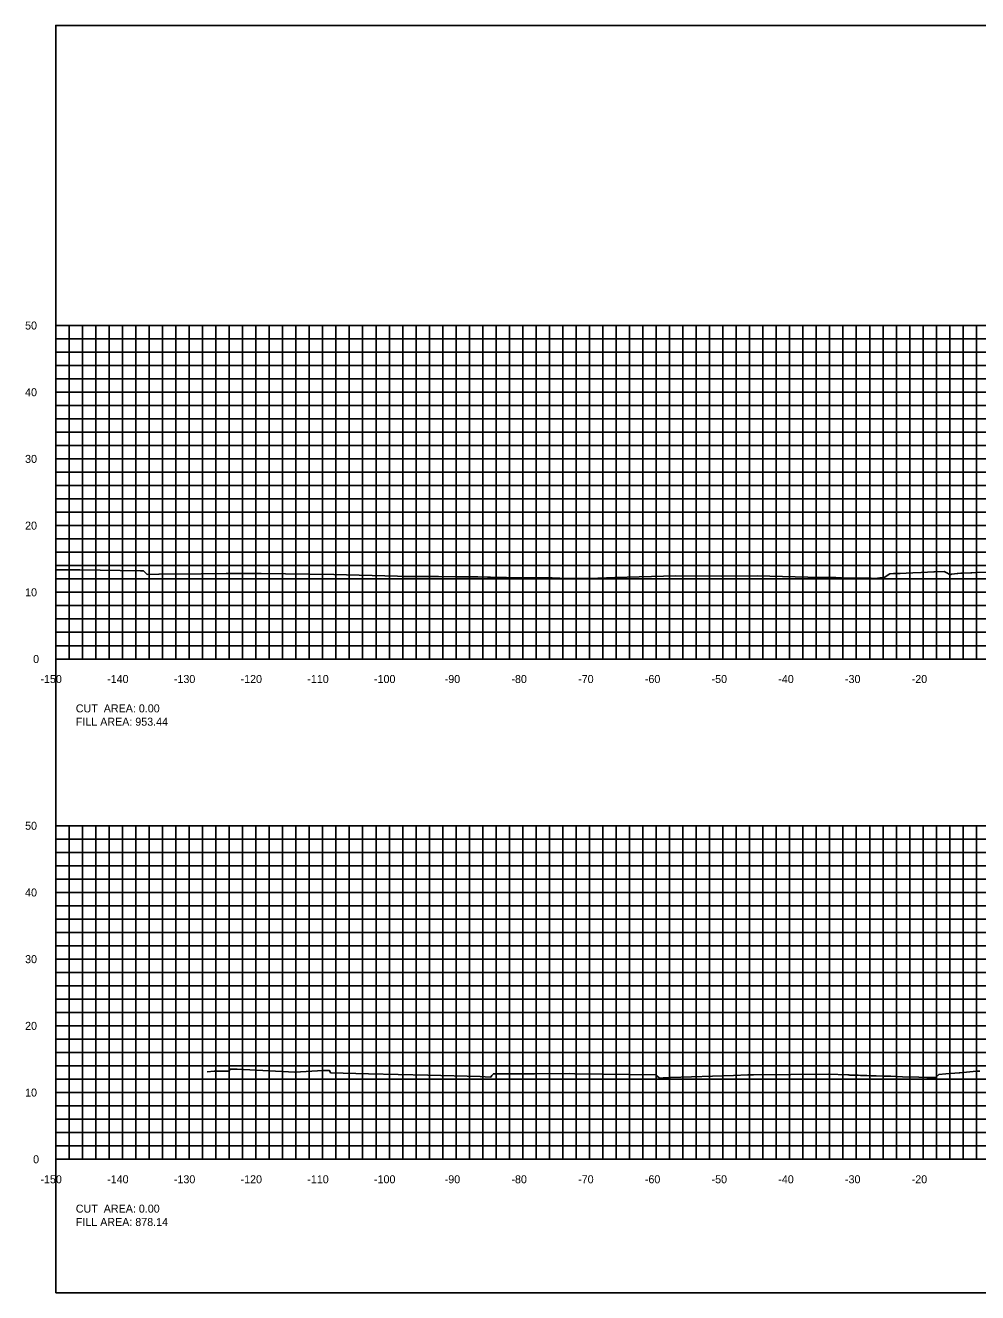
# Model space of a CAD drawing. Extents: x 1797714 to 1804825, y 249015 to 250269.
# Drawn here: x 1804176.4 to 1804319.2, y 250079.4 to 250269.4 of the extents above; entities that cross this region are included whole.
import ezdxf

# ---------------------------------------------------------------- set-up
doc = ezdxf.new("R2010")
doc.units = 0
for name, color, linetype in [('10', 7, 'Continuous'), ('31', 7, 'Continuous'), ('60', 7, 'Continuous'), ('ANNO-TXT', 7, 'Continuous'), ('Level 62', 7, 'Continuous'), ('M-ROADS', 7, 'Continuous')]:
    doc.layers.add(name, color=color, linetype=linetype)

msp = doc.modelspace()

# ---------------------------------------------------------------- linework, layer by layer
msp.add_lwpolyline([(1804181, 250079.43), (1804481, 250079.43), (1804481, 250269.43), (1804181, 250269.43)], close=True)
at = {"layer": '60'}
for p, q in [((1804180.94, 250224.43), (1804181, 250224.43)), ((1804181, 250174.43), (1804181, 250224.43)), ((1804180.94, 250214.43), (1804181, 250214.43)), ((1804180.94, 250204.43), (1804181, 250204.43)), ((1804180.94, 250194.43), (1804181, 250194.43)), ((1804180.94, 250184.43), (1804181, 250184.43)), ((1804180.94, 250174.43), (1804181, 250174.43)), ((1804181, 250174.43), (1804481, 250174.43)), ((1804181, 250174.37), (1804181, 250174.43)), ((1804191, 250174.37), (1804191, 250174.43)), ((1804201, 250174.37), (1804201, 250174.43)), ((1804211, 250174.37), (1804211, 250174.43)), ((1804221, 250174.37), (1804221, 250174.43)), ((1804231, 250174.37), (1804231, 250174.43)), ((1804241, 250174.37), (1804241, 250174.43)), ((1804251, 250174.37), (1804251, 250174.43)), ((1804261, 250174.37), (1804261, 250174.43)), ((1804271, 250174.37), (1804271, 250174.43)), ((1804281, 250174.37), (1804281, 250174.43)), ((1804291, 250174.37), (1804291, 250174.43)), ((1804301, 250174.37), (1804301, 250174.43)), ((1804311, 250174.37), (1804311, 250174.43)), ((1804180.94, 250149.43), (1804181, 250149.43)), ((1804181, 250099.43), (1804181, 250149.43)), ((1804180.94, 250139.43), (1804181, 250139.43)), ((1804180.94, 250129.43), (1804181, 250129.43)), ((1804180.94, 250119.43), (1804181, 250119.43)), ((1804180.94, 250109.43), (1804181, 250109.43)), ((1804180.94, 250099.43), (1804181, 250099.43)), ((1804181, 250099.43), (1804481, 250099.43)), ((1804181, 250099.37), (1804181, 250099.43)), ((1804191, 250099.37), (1804191, 250099.43)), ((1804201, 250099.37), (1804201, 250099.43)), ((1804211, 250099.37), (1804211, 250099.43)), ((1804221, 250099.37), (1804221, 250099.43)), ((1804231, 250099.37), (1804231, 250099.43)), ((1804241, 250099.37), (1804241, 250099.43)), ((1804251, 250099.37), (1804251, 250099.43)), ((1804261, 250099.37), (1804261, 250099.43)), ((1804271, 250099.37), (1804271, 250099.43)), ((1804281, 250099.37), (1804281, 250099.43)), ((1804291, 250099.37), (1804291, 250099.43)), ((1804301, 250099.37), (1804301, 250099.43)), ((1804311, 250099.37), (1804311, 250099.43))]:
    msp.add_line(p, q, dxfattribs=at)
at = {"layer": 'Level 62'}
for p, q in [((1804181, 250224.43), (1804481, 250224.43)), ((1804181, 250174.43), (1804181, 250224.43)), ((1804183, 250174.43), (1804183, 250224.43)), ((1804185, 250174.43), (1804185, 250224.43)), ((1804187, 250174.43), (1804187, 250224.43)), ((1804189, 250174.43), (1804189, 250224.43)), ((1804191, 250174.43), (1804191, 250224.43)), ((1804193, 250174.43), (1804193, 250224.43)), ((1804195, 250174.43), (1804195, 250224.43)), ((1804197, 250174.43), (1804197, 250224.43)), ((1804199, 250174.43), (1804199, 250224.43)), ((1804201, 250174.43), (1804201, 250224.43)), ((1804203, 250174.43), (1804203, 250224.43)), ((1804205, 250174.43), (1804205, 250224.43)), ((1804207, 250174.43), (1804207, 250224.43)), ((1804209, 250174.43), (1804209, 250224.43)), ((1804211, 250174.43), (1804211, 250224.43)), ((1804213, 250174.43), (1804213, 250224.43)), ((1804215, 250174.43), (1804215, 250224.43)), ((1804217, 250174.43), (1804217, 250224.43)), ((1804219, 250174.43), (1804219, 250224.43)), ((1804221, 250174.43), (1804221, 250224.43)), ((1804223, 250174.43), (1804223, 250224.43)), ((1804225, 250174.43), (1804225, 250224.43)), ((1804227, 250174.43), (1804227, 250224.43)), ((1804229, 250174.43), (1804229, 250224.43)), ((1804231, 250174.43), (1804231, 250224.43)), ((1804233, 250174.43), (1804233, 250224.43)), ((1804235, 250174.43), (1804235, 250224.43)), ((1804237, 250174.43), (1804237, 250224.43)), ((1804239, 250174.43), (1804239, 250224.43)), ((1804241, 250174.43), (1804241, 250224.43)), ((1804243, 250174.43), (1804243, 250224.43)), ((1804245, 250174.43), (1804245, 250224.43)), ((1804247, 250174.43), (1804247, 250224.43)), ((1804249, 250174.43), (1804249, 250224.43)), ((1804251, 250174.43), (1804251, 250224.43)), ((1804253, 250174.43), (1804253, 250224.43)), ((1804255, 250174.43), (1804255, 250224.43)), ((1804257, 250174.43), (1804257, 250224.43)), ((1804259, 250174.43), (1804259, 250224.43)), ((1804261, 250174.43), (1804261, 250224.43)), ((1804263, 250174.43), (1804263, 250224.43)), ((1804265, 250174.43), (1804265, 250224.43)), ((1804267, 250174.43), (1804267, 250224.43)), ((1804269, 250174.43), (1804269, 250224.43)), ((1804271, 250174.43), (1804271, 250224.43)), ((1804273, 250174.43), (1804273, 250224.43)), ((1804275, 250174.43), (1804275, 250224.43)), ((1804277, 250174.43), (1804277, 250224.43)), ((1804279, 250174.43), (1804279, 250224.43)), ((1804281, 250174.43), (1804281, 250224.43)), ((1804283, 250174.43), (1804283, 250224.43)), ((1804285, 250174.43), (1804285, 250224.43)), ((1804287, 250174.43), (1804287, 250224.43)), ((1804289, 250174.43), (1804289, 250224.43)), ((1804291, 250174.43), (1804291, 250224.43)), ((1804293, 250174.43), (1804293, 250224.43)), ((1804295, 250174.43), (1804295, 250224.43)), ((1804297, 250174.43), (1804297, 250224.43)), ((1804299, 250174.43), (1804299, 250224.43)), ((1804301, 250174.43), (1804301, 250224.43)), ((1804303, 250174.43), (1804303, 250224.43)), ((1804305, 250174.43), (1804305, 250224.43)), ((1804307, 250174.43), (1804307, 250224.43)), ((1804309, 250174.43), (1804309, 250224.43)), ((1804311, 250174.43), (1804311, 250224.43)), ((1804313, 250174.43), (1804313, 250224.43)), ((1804315, 250174.43), (1804315, 250224.43)), ((1804317, 250174.43), (1804317, 250224.43)), ((1804319, 250174.43), (1804319, 250224.43)), ((1804181, 250222.43), (1804481, 250222.43)), ((1804181, 250220.43), (1804481, 250220.43)), ((1804181, 250218.43), (1804481, 250218.43)), ((1804181, 250216.43), (1804481, 250216.43)), ((1804181, 250214.43), (1804481, 250214.43)), ((1804181, 250212.43), (1804481, 250212.43)), ((1804181, 250210.43), (1804481, 250210.43)), ((1804181, 250208.43), (1804481, 250208.43)), ((1804181, 250206.43), (1804481, 250206.43)), ((1804181, 250204.43), (1804481, 250204.43)), ((1804181, 250202.43), (1804481, 250202.43)), ((1804181, 250200.43), (1804481, 250200.43)), ((1804181, 250198.43), (1804481, 250198.43)), ((1804181, 250196.43), (1804481, 250196.43)), ((1804181, 250194.43), (1804481, 250194.43)), ((1804181, 250192.43), (1804481, 250192.43)), ((1804181, 250190.43), (1804481, 250190.43)), ((1804181, 250188.43), (1804481, 250188.43)), ((1804181, 250186.43), (1804481, 250186.43)), ((1804181, 250184.43), (1804481, 250184.43)), ((1804181, 250182.43), (1804481, 250182.43)), ((1804181, 250180.43), (1804481, 250180.43)), ((1804181, 250178.43), (1804481, 250178.43)), ((1804181, 250176.43), (1804481, 250176.43)), ((1804181, 250174.43), (1804481, 250174.43)), ((1804181, 250149.43), (1804481, 250149.43)), ((1804181, 250099.43), (1804181, 250149.43)), ((1804183, 250099.43), (1804183, 250149.43)), ((1804185, 250099.43), (1804185, 250149.43)), ((1804187, 250099.43), (1804187, 250149.43)), ((1804189, 250099.43), (1804189, 250149.43)), ((1804191, 250099.43), (1804191, 250149.43)), ((1804193, 250099.43), (1804193, 250149.43)), ((1804195, 250099.43), (1804195, 250149.43)), ((1804197, 250099.43), (1804197, 250149.43)), ((1804199, 250099.43), (1804199, 250149.43)), ((1804201, 250099.43), (1804201, 250149.43)), ((1804203, 250099.43), (1804203, 250149.43)), ((1804205, 250099.43), (1804205, 250149.43)), ((1804207, 250099.43), (1804207, 250149.43)), ((1804209, 250099.43), (1804209, 250149.43)), ((1804211, 250099.43), (1804211, 250149.43)), ((1804213, 250099.43), (1804213, 250149.43)), ((1804215, 250099.43), (1804215, 250149.43)), ((1804217, 250099.43), (1804217, 250149.43)), ((1804219, 250099.43), (1804219, 250149.43)), ((1804221, 250099.43), (1804221, 250149.43)), ((1804223, 250099.43), (1804223, 250149.43)), ((1804225, 250099.43), (1804225, 250149.43)), ((1804227, 250099.43), (1804227, 250149.43)), ((1804229, 250099.43), (1804229, 250149.43)), ((1804231, 250099.43), (1804231, 250149.43)), ((1804233, 250099.43), (1804233, 250149.43)), ((1804235, 250099.43), (1804235, 250149.43)), ((1804237, 250099.43), (1804237, 250149.43)), ((1804239, 250099.43), (1804239, 250149.43)), ((1804241, 250099.43), (1804241, 250149.43)), ((1804243, 250099.43), (1804243, 250149.43)), ((1804245, 250099.43), (1804245, 250149.43)), ((1804247, 250099.43), (1804247, 250149.43)), ((1804249, 250099.43), (1804249, 250149.43)), ((1804251, 250099.43), (1804251, 250149.43)), ((1804253, 250099.43), (1804253, 250149.43)), ((1804255, 250099.43), (1804255, 250149.43)), ((1804257, 250099.43), (1804257, 250149.43)), ((1804259, 250099.43), (1804259, 250149.43)), ((1804261, 250099.43), (1804261, 250149.43)), ((1804263, 250099.43), (1804263, 250149.43)), ((1804265, 250099.43), (1804265, 250149.43)), ((1804267, 250099.43), (1804267, 250149.43)), ((1804269, 250099.43), (1804269, 250149.43)), ((1804271, 250099.43), (1804271, 250149.43)), ((1804273, 250099.43), (1804273, 250149.43)), ((1804275, 250099.43), (1804275, 250149.43)), ((1804277, 250099.43), (1804277, 250149.43)), ((1804279, 250099.43), (1804279, 250149.43)), ((1804281, 250099.43), (1804281, 250149.43)), ((1804283, 250099.43), (1804283, 250149.43)), ((1804285, 250099.43), (1804285, 250149.43)), ((1804287, 250099.43), (1804287, 250149.43)), ((1804289, 250099.43), (1804289, 250149.43)), ((1804291, 250099.43), (1804291, 250149.43)), ((1804293, 250099.43), (1804293, 250149.43)), ((1804295, 250099.43), (1804295, 250149.43)), ((1804297, 250099.43), (1804297, 250149.43)), ((1804299, 250099.43), (1804299, 250149.43)), ((1804301, 250099.43), (1804301, 250149.43)), ((1804303, 250099.43), (1804303, 250149.43)), ((1804305, 250099.43), (1804305, 250149.43)), ((1804307, 250099.43), (1804307, 250149.43)), ((1804309, 250099.43), (1804309, 250149.43)), ((1804311, 250099.43), (1804311, 250149.43)), ((1804313, 250099.43), (1804313, 250149.43)), ((1804315, 250099.43), (1804315, 250149.43)), ((1804317, 250099.43), (1804317, 250149.43)), ((1804319, 250099.43), (1804319, 250149.43)), ((1804181, 250147.43), (1804481, 250147.43)), ((1804181, 250145.43), (1804481, 250145.43)), ((1804181, 250143.43), (1804481, 250143.43)), ((1804181, 250141.43), (1804481, 250141.43)), ((1804181, 250139.43), (1804481, 250139.43)), ((1804181, 250137.43), (1804481, 250137.43)), ((1804181, 250135.43), (1804481, 250135.43)), ((1804181, 250133.43), (1804481, 250133.43)), ((1804181, 250131.43), (1804481, 250131.43)), ((1804181, 250129.43), (1804481, 250129.43)), ((1804181, 250127.43), (1804481, 250127.43)), ((1804181, 250125.43), (1804481, 250125.43)), ((1804181, 250123.43), (1804481, 250123.43)), ((1804181, 250121.43), (1804481, 250121.43)), ((1804181, 250119.43), (1804481, 250119.43)), ((1804181, 250117.43), (1804481, 250117.43)), ((1804181, 250115.43), (1804481, 250115.43)), ((1804181, 250113.43), (1804481, 250113.43)), ((1804181, 250111.43), (1804481, 250111.43)), ((1804181, 250109.43), (1804481, 250109.43)), ((1804181, 250107.43), (1804481, 250107.43)), ((1804181, 250105.43), (1804481, 250105.43)), ((1804181, 250103.43), (1804481, 250103.43)), ((1804181, 250101.43), (1804481, 250101.43)), ((1804181, 250099.43), (1804481, 250099.43))]:
    msp.add_line(p, q, dxfattribs=at)
at = {"layer": 'M-ROADS'}
for points in [[(1804181, 250187.82), (1804184.59, 250187.78), (1804193.71, 250187.67), (1804194.13, 250187.66), (1804194.66, 250187.13), (1804194.68, 250187.11), (1804196.43, 250187.16), (1804196.5, 250187.16), (1804202.8, 250187.21), (1804206.53, 250187.24), (1804207.9, 250187.24), (1804208.44, 250187.25), (1804209.12, 250187.25), (1804211.79, 250187.25), (1804222.67, 250187.08), (1804232.2, 250186.83), (1804233.13, 250186.82), (1804234.22, 250186.81), (1804236.94, 250186.79), (1804238.38, 250186.78), (1804241.05, 250186.74), (1804242.72, 250186.74), (1804243.89, 250186.74), (1804244.09, 250186.74), (1804244.26, 250186.73), (1804245.73, 250186.69), (1804246.18, 250186.68), (1804247.1, 250186.66), (1804247.45, 250186.65), (1804248.18, 250186.64), (1804248.31, 250186.64), (1804248.55, 250186.64), (1804250.03, 250186.62), (1804250.14, 250186.62), (1804250.89, 250186.61), (1804251.24, 250186.61), (1804252.56, 250186.6), (1804253.55, 250186.6), (1804254.06, 250186.6), (1804255.2, 250186.6), (1804255.42, 250186.59), (1804257.7, 250186.52), (1804257.74, 250186.52), (1804257.77, 250186.52), (1804259.37, 250186.49), (1804259.48, 250186.5), (1804261.02, 250186.52), (1804264.82, 250186.63), (1804273.92, 250186.89), (1804280.86, 250186.86), (1804286.13, 250186.89), (1804295.64, 250186.67), (1804296.13, 250186.66), (1804296.66, 250186.65), (1804297.25, 250186.64), (1804297.92, 250186.63), (1804298.66, 250186.62), (1804298.79, 250186.62), (1804301.18, 250186.54), (1804301.64, 250186.54), (1804301.64, 250186.54), (1804301.85, 250186.55), (1804302.27, 250186.57), (1804302.92, 250186.57), (1804303.06, 250186.55), (1804303.2, 250186.54), (1804303.52, 250186.51), (1804303.62, 250186.51), (1804303.72, 250186.52), (1804304.15, 250186.57), (1804305.29, 250186.68), (1804305.49, 250186.86), (1804306.02, 250187.2), (1804306.57, 250187.23), (1804307.55, 250187.27), (1804308.46, 250187.31), (1804309.46, 250187.35), (1804310.73, 250187.4), (1804312.6, 250187.49), (1804312.73, 250187.49), (1804314.15, 250187.57), (1804314.46, 250187.41), (1804315, 250187.1), (1804315.15, 250187.12), (1804315.26, 250187.14), (1804315.74, 250187.19), (1804316.1, 250187.23), (1804316.21, 250187.24), (1804316.64, 250187.28), (1804316.91, 250187.32), (1804317.02, 250187.32), (1804318.15, 250187.36), (1804318.29, 250187.35), (1804319.06, 250187.39), (1804326.79, 250187.61)], [(1804203.69, 250112.55), (1804204.76, 250112.62), (1804206.47, 250112.63), (1804207, 250112.62), (1804207.1, 250112.92), (1804207.11, 250112.93), (1804207.14, 250112.93), (1804208.19, 250112.94), (1804216.83, 250112.5), (1804221.1, 250112.74), (1804221.72, 250112.72), (1804222.03, 250112.72), (1804222.07, 250112.63), (1804222.2, 250112.39), (1804227.88, 250112.24), (1804236.75, 250112.04), (1804244.62, 250111.84), (1804245.34, 250111.79), (1804246.19, 250111.76), (1804246.37, 250112.01), (1804246.59, 250112.25), (1804252.74, 250112.23), (1804257.94, 250112.31), (1804258.78, 250112.26), (1804267.04, 250112.15), (1804270.96, 250112.08), (1804271.11, 250111.92), (1804271.52, 250111.59), (1804272.05, 250111.62), (1804273.12, 250111.68), (1804282.58, 250112), (1804284.74, 250112.09), (1804285.61, 250112.1), (1804296.76, 250112.18), (1804299.71, 250112.07), (1804299.86, 250112.07), (1804300.04, 250112.06), (1804300.23, 250112.06), (1804300.44, 250112.05), (1804300.68, 250112.04), (1804300.96, 250112.03), (1804301.27, 250112.02), (1804301.64, 250112.01), (1804302.07, 250112), (1804302.58, 250111.98), (1804303.2, 250111.96), (1804303.96, 250111.94), (1804304.92, 250111.91), (1804306.19, 250111.87), (1804307.9, 250111.81), (1804310.38, 250111.74), (1804311.57, 250111.7), (1804311.73, 250111.69), (1804312.02, 250111.69), (1804312.2, 250111.68), (1804312.32, 250111.68), (1804312.41, 250111.68), (1804312.47, 250111.68), (1804312.52, 250111.67), (1804312.56, 250111.67), (1804312.6, 250111.67), (1804312.63, 250111.67), (1804312.65, 250111.67), (1804312.67, 250111.67), (1804312.89, 250111.67), (1804313.3, 250112.1), (1804313.39, 250112.15), (1804314.44, 250112.22), (1804316.41, 250112.4), (1804316.52, 250112.41), (1804319, 250112.66), (1804319.11, 250112.66), (1804319.51, 250112.66)]]:
    msp.add_lwpolyline(points, dxfattribs=at)

# ---------------------------------------------------------------- texts
at = {"layer": '10'}
for s, p in [('-150', (1804178.7, 250170.83)), ('-140', (1804188.7, 250170.83)), ('-130', (1804198.7, 250170.83)), ('-120', (1804208.7, 250170.83)), ('-110', (1804218.7, 250170.83)), ('-100', (1804228.7, 250170.83)), ('-90', (1804239.3, 250170.83)), ('-80', (1804249.3, 250170.83)), ('-70', (1804259.3, 250170.83)), ('-60', (1804269.3, 250170.83)), ('-50', (1804279.3, 250170.83)), ('-40', (1804289.3, 250170.83)), ('-30', (1804299.3, 250170.83)), ('-20', (1804309.3, 250170.83)), ('-150', (1804178.7, 250095.83)), ('-140', (1804188.7, 250095.83)), ('-130', (1804198.7, 250095.83)), ('-120', (1804208.7, 250095.83)), ('-110', (1804218.7, 250095.83)), ('-100', (1804228.7, 250095.83)), ('-90', (1804239.3, 250095.83)), ('-80', (1804249.3, 250095.83)), ('-70', (1804259.3, 250095.83)), ('-60', (1804269.3, 250095.83)), ('-50', (1804279.3, 250095.83)), ('-40', (1804289.3, 250095.83)), ('-30', (1804299.3, 250095.83)), ('-20', (1804309.3, 250095.83))]:
    msp.add_text(s, height=1.2, dxfattribs=at).set_placement(p)
at = {"layer": '31'}
for s, p in [('50', (1804176.4, 250223.83)), ('40', (1804176.4, 250213.83)), ('30', (1804176.4, 250203.83)), ('20', (1804176.4, 250193.83)), ('10', (1804176.4, 250183.83)), ('0', (1804177.6, 250173.83)), ('50', (1804176.4, 250148.83)), ('40', (1804176.4, 250138.83)), ('30', (1804176.4, 250128.83)), ('20', (1804176.4, 250118.83)), ('10', (1804176.4, 250108.83)), ('0', (1804177.6, 250098.83))]:
    msp.add_text(s, height=1.2, dxfattribs=at).set_placement(p)
at = {"layer": '60'}
for p in [(1804181, 250174.43), (1804181, 250099.43)]:
    msp.add_text('-', height=0.0001, dxfattribs=at).set_placement(p)
at = {"layer": 'ANNO-TXT'}
for s, p in [('CUT  AREA: 0.00', (1804184, 250166.43)), ('FILL AREA: 953.44', (1804184, 250164.43)), ('CUT  AREA: 0.00', (1804184, 250091.43)), ('FILL AREA: 878.14', (1804184, 250089.43))]:
    msp.add_text(s, height=1.2, dxfattribs=at).set_placement(p)

doc.saveas('drawing.dxf')
